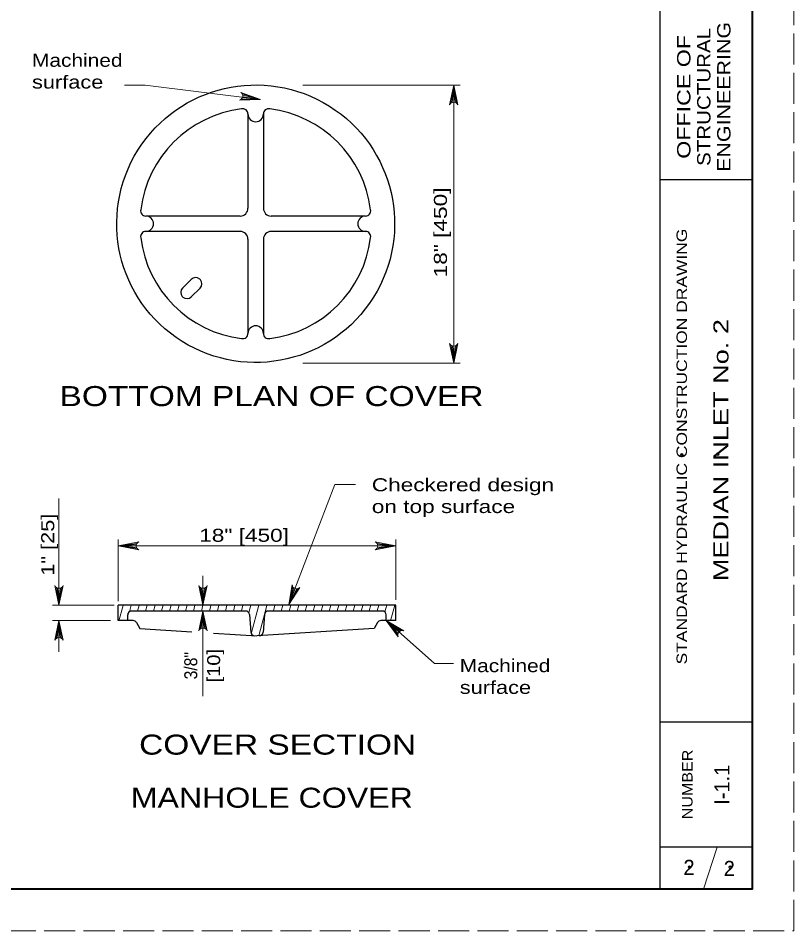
# Model space of a CAD drawing. Extents: x 339.1 to 373.1, y 1412.7 to 1456.7.
# Drawn here: x 363.76 to 373.06, y 1412.75 to 1423.68 of the extents above; entities that cross this region are included whole.
import ezdxf
from ezdxf.enums import TextEntityAlignment as Align

# ---------------------------------------------------------------- set-up
doc = ezdxf.new("R2010")
doc.units = 0
doc.header["$LTSCALE"] = 0.062
doc.header["$PDMODE"] = 32
doc.header["$PDSIZE"] = 0.031
doc.linetypes.add('LONG_DASHED', pattern=[7.5, 6, -1.5])
doc.layers.add('1', color=7, linetype='Continuous', lineweight=13)

msp = doc.modelspace()

# ---------------------------------------------------------------- linework, layer by layer
at = {"layer": '1', "lineweight": 25}
for p, q in [((371.4605, 1413.2455), (371.4605, 1434.2455)), ((372.5605, 1434.2455), (372.5605, 1413.2455)), ((366.51808, 1422.53492), (366.51808, 1421.40433)), ((366.70308, 1422.53492), (366.70308, 1421.40433)), ((372.5605, 1421.7455), (371.4605, 1421.7455)), ((366.42558, 1421.31192), (365.29358, 1421.31192)), ((367.92758, 1421.31192), (366.79575, 1421.31192)), ((366.42558, 1421.12717), (365.29358, 1421.12717)), ((367.92758, 1421.12717), (366.79558, 1421.12717)), ((366.51808, 1421.03475), (366.51808, 1419.90417)), ((366.70308, 1421.03475), (366.70308, 1419.90417)), ((365.83867, 1420.55308), (365.73408, 1420.44858)), ((365.94325, 1420.44858), (365.83867, 1420.34408)), ((364.96067, 1416.65), (368.291, 1416.65)), ((364.96067, 1416.46233), (364.96067, 1416.64708)), ((366.49042, 1416.57783), (365.1225, 1416.57783)), ((368.12917, 1416.57783), (366.76125, 1416.57783)), ((368.291, 1416.46233), (368.291, 1416.64708)), ((365.14208, 1416.46233), (364.96067, 1416.46233)), ((365.07625, 1416.46233), (365.07625, 1416.53167)), ((366.53667, 1416.53508), (366.55308, 1416.32008)), ((366.715, 1416.53508), (366.69858, 1416.32008)), ((368.291, 1416.46233), (368.10992, 1416.46233)), ((368.17542, 1416.46233), (368.17542, 1416.53167)), ((365.18208, 1416.43917), (365.22225, 1416.36992)), ((365.22225, 1416.36992), (365.84458, 1416.32967)), ((368.02942, 1416.36992), (366.62883, 1416.27933)), ((368.06958, 1416.43917), (368.02942, 1416.36992)), ((366.10333, 1416.31292), (366.62283, 1416.27933)), ((372.5605, 1415.2455), (371.4605, 1415.2455)), ((372.5605, 1413.7455), (371.4605, 1413.7455))]:
    msp.add_line(p, q, dxfattribs=at)
at = {"layer": '1'}
for p, q in [((367.17658, 1422.88008), (369.06375, 1422.88008)), ((368.95017, 1422.66433), (368.98508, 1422.88008)), ((368.96483, 1422.6725), (368.98508, 1422.88008)), ((368.98508, 1422.67625), (368.98508, 1422.88008)), ((369.00108, 1422.67408), (368.98508, 1422.88008)), ((369.01675, 1422.66683), (368.98508, 1422.88008)), ((368.98508, 1422.88008), (368.98508, 1419.54892)), ((366.44133, 1422.71375), (366.6695, 1422.70725)), ((366.44992, 1422.77617), (366.6695, 1422.70725)), ((366.4515, 1422.72708), (366.6695, 1422.70725)), ((366.456, 1422.76117), (366.6695, 1422.70725)), ((366.4565, 1422.74158), (366.6695, 1422.70725)), ((368.9535, 1419.76217), (368.98508, 1419.54892)), ((368.96917, 1419.755), (368.98508, 1419.54892)), ((369.02008, 1419.76467), (368.98508, 1419.54892)), ((369.00542, 1419.7565), (368.98508, 1419.54892)), ((368.98508, 1419.75275), (368.98508, 1419.54892)), ((367.17658, 1419.54892), (369.06375, 1419.54892)), ((364.25267, 1416.64708), (364.25267, 1417.92833)), ((364.96067, 1416.69417), (364.96067, 1417.43667)), ((365.18675, 1417.38792), (364.96067, 1417.358)), ((365.17908, 1417.37308), (364.96067, 1417.358)), ((365.17675, 1417.358), (364.96067, 1417.358)), ((365.18075, 1417.33892), (364.96067, 1417.358)), ((365.18942, 1417.32508), (364.96067, 1417.358)), ((364.96067, 1417.358), (368.291, 1417.358)), ((368.06225, 1417.32508), (368.291, 1417.358)), ((368.06492, 1417.38792), (368.291, 1417.358)), ((368.07092, 1417.33892), (368.291, 1417.358)), ((368.07258, 1417.37308), (368.291, 1417.358)), ((368.07492, 1417.358), (368.291, 1417.358)), ((368.291, 1416.71267), (368.291, 1417.43667)), ((365.97867, 1416.64675), (365.97867, 1416.99967)), ((364.221, 1416.86033), (364.25267, 1416.64708)), ((364.23667, 1416.85317), (364.25267, 1416.64708)), ((364.28758, 1416.86292), (364.25267, 1416.64708)), ((364.27292, 1416.85475), (364.25267, 1416.64708)), ((364.25267, 1416.85092), (364.25267, 1416.64708)), ((365.947, 1416.86), (365.97867, 1416.64675)), ((365.96267, 1416.85275), (365.97867, 1416.64675)), ((366.01358, 1416.8625), (365.97867, 1416.64675)), ((365.99892, 1416.85433), (365.97867, 1416.64675)), ((365.97867, 1416.85058), (365.97867, 1416.64675)), ((367.05658, 1416.866), (367.00917, 1416.65583)), ((367.06867, 1416.854), (367.00917, 1416.65583)), ((367.08292, 1416.84658), (367.00917, 1416.65583)), ((367.12, 1416.84608), (367.00917, 1416.65583)), ((367.10333, 1416.84333), (367.00917, 1416.65583)), ((364.91325, 1416.64708), (364.174, 1416.64708)), ((364.971, 1416.46017), (365.02075, 1416.64558)), ((365.09617, 1416.56983), (365.11733, 1416.64808)), ((365.19375, 1416.5765), (365.21225, 1416.64558)), ((365.28925, 1416.57525), (365.30825, 1416.646)), ((365.38542, 1416.5775), (365.40433, 1416.64742)), ((365.48142, 1416.57825), (365.49975, 1416.64625)), ((365.57717, 1416.57783), (365.59575, 1416.64767)), ((365.67258, 1416.57675), (365.6915, 1416.64708)), ((365.76808, 1416.57567), (365.78733, 1416.64733)), ((365.86425, 1416.57783), (365.88275, 1416.64658)), ((365.94367, 1416.36158), (365.97867, 1416.57733)), ((365.95833, 1416.36975), (365.97867, 1416.57733)), ((365.96008, 1416.57758), (365.97867, 1416.64675)), ((365.97867, 1415.55817), (365.97867, 1416.57733)), ((365.97867, 1416.3735), (365.97867, 1416.57733)), ((365.99458, 1416.37133), (365.97867, 1416.57733)), ((366.01025, 1416.36408), (365.97867, 1416.57733)), ((366.056, 1416.57758), (366.07408, 1416.64525)), ((366.15217, 1416.579), (366.17008, 1416.64625)), ((366.24692, 1416.57567), (366.26592, 1416.64658)), ((366.34283, 1416.57617), (366.362, 1416.64733)), ((366.43933, 1416.57833), (366.45817, 1416.64842)), ((366.53008, 1416.5595), (366.55333, 1416.646)), ((366.5575, 1416.30517), (366.64917, 1416.64658)), ((366.64658, 1416.27975), (366.74425, 1416.644)), ((366.82258, 1416.57825), (366.84108, 1416.64742)), ((366.91783, 1416.57758), (366.93667, 1416.64767)), ((367.01317, 1416.5745), (367.03242, 1416.64633)), ((367.1095, 1416.5775), (367.12833, 1416.64742)), ((367.20517, 1416.57758), (367.22417, 1416.64817)), ((367.301, 1416.57725), (367.31992, 1416.64742)), ((367.39692, 1416.5775), (367.41625, 1416.64967)), ((367.49283, 1416.57783), (367.51158, 1416.64767)), ((367.58892, 1416.57942), (367.60758, 1416.64858)), ((367.68442, 1416.57783), (367.703, 1416.64733)), ((367.78, 1416.57758), (367.7985, 1416.64633)), ((367.87575, 1416.57683), (367.89383, 1416.64483)), ((367.97158, 1416.57825), (367.9915, 1416.6525)), ((368.0675, 1416.57908), (368.08567, 1416.64675)), ((368.16042, 1416.568), (368.18133, 1416.646)), ((368.22725, 1416.46042), (368.27733, 1416.64708)), ((364.8705, 1416.46233), (364.174, 1416.46233)), ((364.21767, 1416.2465), (364.25267, 1416.46233)), ((364.23233, 1416.25467), (364.25267, 1416.46233)), ((364.25267, 1416.08808), (364.25267, 1416.46233)), ((364.25267, 1416.25842), (364.25267, 1416.46233)), ((364.26867, 1416.25625), (364.25267, 1416.46233)), ((364.28425, 1416.249), (364.25267, 1416.46233)), ((368.329, 1416.32675), (368.17542, 1416.46233)), ((368.318, 1416.3095), (368.17542, 1416.46233)), ((368.31417, 1416.29342), (368.17542, 1416.46233)), ((368.34158, 1416.33683), (368.17542, 1416.46233)), ((368.35767, 1416.34342), (368.17542, 1416.46233)), ((371.97717, 1413.2455), (372.14383, 1413.7455))]:
    msp.add_line(p, q, dxfattribs=at)
at = {"layer": '1', "linetype": 'LONG_DASHED'}
msp.add_lwpolyline([(339.0605, 1412.7455), (373.0605, 1412.7455), (373.0605, 1434.7455), (339.0605, 1434.7455)], close=True, dxfattribs=at)
at = {"layer": '1', "lineweight": 25}
msp.add_lwpolyline([(372.5605, 1413.2455), (341.0605, 1413.2455), (341.0605, 1434.2455)], dxfattribs=at)
at = {"layer": '1', "lineweight": 40}
msp.add_lwpolyline([(341.0605, 1434.2455), (372.5605, 1434.2455), (372.5605, 1413.2455), (341.0605, 1413.2455)], close=True, dxfattribs=at)
at = {"layer": '1'}
for points in [[(366.6695, 1422.70725), (365.28642, 1422.88217), (365.039, 1422.88217)], [(368.93517, 1422.6445), (368.98508, 1422.88008), (369.03508, 1422.6445)], [(366.43175, 1422.79342), (366.6695, 1422.70725), (366.41492, 1422.7005)], [(369.03508, 1419.7845), (368.98508, 1419.54892), (368.93517, 1419.7845)], [(367.00917, 1416.65583), (367.55992, 1418.09375), (367.80625, 1418.09375)], [(365.21033, 1417.31092), (364.96067, 1417.358), (365.21033, 1417.40517)], [(368.04133, 1417.31092), (368.291, 1417.358), (368.04133, 1417.40517)], [(364.30258, 1416.88267), (364.25267, 1416.64708), (364.20267, 1416.88267)], [(366.02858, 1416.88233), (365.97867, 1416.64675), (365.92867, 1416.88233)], [(367.14125, 1416.85958), (367.00917, 1416.65583), (367.04742, 1416.893)], [(365.92867, 1416.34175), (365.97867, 1416.57733), (366.02858, 1416.34175)], [(364.20267, 1416.22667), (364.25267, 1416.46233), (364.30258, 1416.22667)], [(368.31883, 1416.26942), (368.17542, 1416.46233), (368.38692, 1416.34183)], [(368.17542, 1416.46233), (368.75392, 1415.94875), (368.98133, 1415.94875)]]:
    msp.add_lwpolyline(points, dxfattribs=at)
at = {"layer": '1', "lineweight": 25}
for centre, major_axis, start_param, end_param in [((366.61059, 1421.21955), (-1.66519, 0), 1.01182797, 7.29501323), ((366.61059, 1421.21955), (-1.38766, 0), 4.83375452, 6.16181977), ((366.4564, 1422.53493), (-0.06185, 0), 3.14159265, 4.93704985), ((366.76477, 1422.53493), (-0.06185, 0), 4.48772811, 6.28318531), ((366.61059, 1421.21955), (-1.38766, 0), 3.2629582, 4.59102344), ((366.61059, 1422.53493), (-0.09251, 0), 6.28318521, 9.42477782), ((365.2936, 1421.37354), (-0.06185, 0), 6.05852444, 7.85398163), ((366.42557, 1421.40434), (-0.09251, 0), 1.57079647, 3.14159275), ((366.79561, 1421.40434), (0.09251, 0), 3.1415928, 4.71238908), ((367.92758, 1421.37354), (0.06185, 0), 4.71238898, 6.50784617), ((365.29349, 1421.21955), (0.09251, 0), 4.71238883, 7.85398144), ((367.92757, 1421.21955), (-0.09251, 0), 4.71238893, 7.85398154), ((365.2936, 1421.06555), (-0.06185, 0), 4.71238898, 6.50784617), ((366.61059, 1421.21955), (-1.38766, 0), 0.12136554, 1.44943078), ((366.42557, 1421.03475), (-0.09251, 0), 3.14159261, 4.71238888), ((366.79561, 1421.03475), (-0.09251, 0), 4.71238893, 6.28318521), ((366.61059, 1421.21955), (-1.38766, 0), 1.69216187, 3.02022711), ((367.92758, 1421.06555), (0.06185, 0), 6.05852444, 7.85398163), ((365.89106, 1420.50083), (-0.07413, 0), 4.00366599, 5.49778714), ((366.61059, 1421.21955), (-0.94361, 0), 0.77942002, 0.7913763), ((365.89099, 1420.50089), (0.07413, 0), 5.49778714, 6.9919083), ((365.7864, 1420.39629), (-0.07416, 0), 5.49778714, 6.9745732), ((366.61059, 1421.21955), (-1.23964, 0), 0.77980763, 0.7909887), ((365.78633, 1420.39636), (0.07416, 0), 4.02100109, 5.49778714), ((366.61047, 1419.90417), (0.09251, 0), 6.28318511, 9.42477772), ((366.4564, 1419.90416), (0.06185, 0), 4.48772811, 6.28318531), ((366.76477, 1419.90416), (-0.06185, 0), 0, 1.79545719), ((365.12254, 1416.53159), (-0.04626, 0), 4.71238888, 6.28318516), ((366.49049, 1416.53159), (-0.04626, 0), 3.21836445, 4.71238888), ((366.76118, 1416.53159), (-0.04626, 0), 4.71238908, 6.20641351), ((368.12913, 1416.53159), (-0.04626, 0), 3.14159261, 4.71238888), ((365.1421, 1416.41609), (-0.04626, 0), 3.66567847, 4.71238888), ((368.10958, 1416.41609), (-0.04626, 0), 4.71238908, 5.75974221), ((366.59897, 1416.32719), (0.04626, 0), 3.21796991, 4.64775449), ((366.65269, 1416.32719), (0.04626, 0), 4.77702347, 6.20680805)]:
    msp.add_ellipse(centre, major_axis=major_axis, ratio=0.998785, start_param=start_param, end_param=end_param, dxfattribs=at)
at = {"layer": '1'}
for centre, major_axis, ratio, start_param, end_param in [((366.40348, 1422.75011), (0.0539, 0), 0.943396, 4.92854733, 7.29916047), ((368.98518, 1422.62549), (0.0539, 0), 0.943396, 0.38550522, 2.75611836), ((368.98507, 1419.80352), (-0.0539, 0), 0.943396, 0.38550522, 2.75611836), ((365.23053, 1417.3581), (-0.0539, 0), 0.943396, 5.0978942, 7.46850734), ((368.02112, 1417.3581), (0.0539, 0), 0.943396, 5.09786327, 7.46847641), ((364.25259, 1416.9017), (-0.0539, 0), 0.943396, 0.38550522, 2.75611836), ((365.97857, 1416.90132), (-0.0539, 0), 0.943396, 0.38550522, 2.75611836), ((367.10117, 1416.8941), (-0.0535, 0.00651), 0.943396, 0.15139049, 2.52200363), ((365.97868, 1416.32274), (0.0539, 0), 0.943396, 0.38550522, 2.75611836), ((368.36726, 1416.29302), (0.04596, 0.02815), 0.943396, 0.66749952, 3.03811266), ((364.2527, 1416.20768), (0.0539, 0), 0.943396, 0.38550522, 2.75611836), ((366.62583, 1416.32545), (0.04626, 0), 0.998785, 4.64775464, 4.77702332)]:
    msp.add_ellipse(centre, major_axis=major_axis, ratio=ratio, start_param=start_param, end_param=end_param, dxfattribs=at)
for p in [(371.71792, 1418.4515), (372.15075, 1418.45883), (371.80858, 1413.50925), (372.297, 1413.50825)]:
    msp.add_point(p, dxfattribs=at)

# ---------------------------------------------------------------- texts
for s, height, width, p in [('ENGINEERING', 0.16, 1.2, (372.30225, 1422.74004)), ('OFFICE OF', 0.16, 1.3, (371.82225, 1422.73996)), ('STRUCTURAL', 0.16, 1.15, (372.06225, 1422.73996)), ('STANDARD HYDRAULIC CONSTRUCTION DRAWING', 0.125, 1.25, (371.78042, 1418.54954)), ('MEDIAN INLET No. 2', 0.18, 1.35, (372.2775, 1418.50571)), ('3/8"', 0.156, 0.9, (365.91058, 1415.92237)), ('[10]', 0.156, 1.15, (366.18458, 1415.92246)), ('NUMBER', 0.125, 1.15, (371.8475, 1414.49958))]:
    msp.add_text(s, height=height, rotation=90, dxfattribs=dict(at, width=width)).set_placement(p, align=Align.CENTER)
for s, height, width, p in [('Machined', 0.156, 1.2, (363.92933, 1423.10067)), ('surface', 0.156, 1.25, (363.92933, 1422.84)), ('BOTTOM PLAN OF COVER', 0.24, 1.25, (364.25933, 1419.03392)), ('Checkered design', 0.156, 1.3, (368.00233, 1418.01267)), ('on top surface', 0.156, 1.3, (368.00233, 1417.752)), ('18" [450]', 0.156, 1.3, (365.9335, 1417.4075)), ('Machined', 0.156, 1.2, (369.05692, 1415.84492)), ('surface', 0.156, 1.25, (369.05692, 1415.58425)), ('COVER SECTION', 0.24, 1.25, (365.21292, 1414.8565)), ('MANHOLE COVER', 0.24, 1.2, (365.113, 1414.22008))]:
    msp.add_text(s, height=height, dxfattribs=dict(at, width=width)).set_placement(p)
for s, width, p in [('18" [450]', 1.3, (368.90342, 1420.57708)), ('1" [25]', 1.25, (364.19558, 1416.99958))]:
    msp.add_text(s, height=0.156, rotation=90, dxfattribs=dict(at, width=width)).set_placement(p)
msp.add_text('I-1.1', height=0.18, rotation=90, dxfattribs=at).set_placement((372.29, 1414.49583), align=Align.CENTER)
for p in [(371.80496, 1413.41558), (372.28779, 1413.403)]:
    msp.add_text('2', height=0.18, dxfattribs=at).set_placement(p, align=Align.CENTER)

doc.saveas('drawing.dxf')
